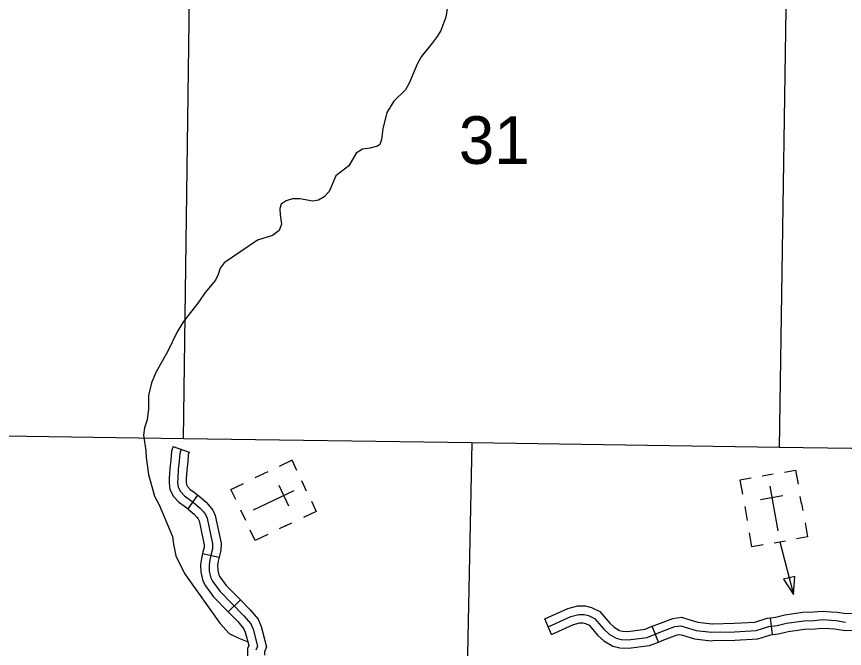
# Model space of a CAD drawing. Extents: x 0 to 3171, y 0 to 2059.
# Drawn here: x 1380.6 to 1502.8, y 562 to 655.3 of the extents above; entities that cross this region are included whole.
import ezdxf

# ---------------------------------------------------------------- set-up
doc = ezdxf.new("R2010")
doc.units = 0
for name, color, linetype in [('Level 32', 7, 'Continuous'), ('Level 35', 7, 'Continuous'), ('Level 4', 7, 'Continuous'), ('Level 45', 7, 'Continuous'), ('Level 5', 7, 'Continuous'), ('Level 57', 7, 'Continuous')]:
    doc.layers.add(name, color=color, linetype=linetype)

msp = doc.modelspace()

# ---------------------------------------------------------------- linework, layer by layer
at = {"layer": 'Level 32'}
for p, q in [((1403.73, 591.84), (1406.08, 591)), ((1405.9, 582.62), (1407.37, 584.64)), ((1408.03, 576.03), (1410.48, 575.52)), ((1411.84, 567.43), (1413.62, 569.18))]:
    msp.add_line(p, q, dxfattribs=at)
for points in [[(1403.73, 591.84), (1403.48, 591.13), (1403.36, 589.81), (1403.21, 588.55), (1403.14, 587.15), (1403.12, 586.49), (1403.21, 585.49), (1403.74, 584.47), (1404.53, 583.63), (1405.36, 583), (1405.9, 582.62)], [(1404.91, 591.42), (1404.71, 590.86), (1404.6, 589.68), (1404.45, 588.45), (1404.39, 587.1), (1404.37, 586.53), (1404.43, 585.85), (1404.77, 585.2), (1405.36, 584.56), (1406.1, 584.01), (1406.71, 583.57), (1407.69, 582.74), (1408.17, 582.17), (1408.47, 581.79), (1408.72, 581.24), (1409.53, 577.45), (1409.51, 576.72), (1409.3, 576), (1409.12, 575.11), (1409.02, 574.36), (1409.04, 573.42), (1409.27, 572.44), (1409.53, 571.94), (1410.58, 570.5), (1414.15, 566.86), (1415.17, 565.65), (1415.53, 564.87), (1416.16, 562.36), (1415.92, 561.76)], [(1406.08, 591), (1405.94, 590.59), (1405.85, 589.55), (1405.7, 588.35), (1405.64, 587.05), (1405.62, 586.56), (1405.66, 586.21), (1405.8, 585.92), (1406.2, 585.5), (1406.84, 585.02), (1407.37, 584.64)], [(1407.37, 584.64), (1407.49, 584.55), (1408.57, 583.63), (1409.14, 582.96), (1409.54, 582.45), (1409.91, 581.64), (1410.79, 577.56), (1410.75, 576.53), (1410.52, 575.7), (1410.48, 575.52)], [(1405.9, 582.62), (1405.94, 582.58), (1406.8, 581.86), (1407.2, 581.38), (1407.39, 581.14), (1407.53, 580.84), (1408.28, 577.34), (1408.26, 576.92), (1408.09, 576.29), (1408.03, 576.03)], [(1408.03, 576.03), (1407.89, 575.32), (1407.76, 574.43), (1407.8, 573.26), (1408.09, 571.99), (1408.47, 571.28), (1409.62, 569.69), (1411.84, 567.43)], [(1410.48, 575.52), (1410.35, 574.9), (1410.27, 574.29), (1410.29, 573.59), (1410.45, 572.88), (1410.6, 572.6), (1411.53, 571.31), (1413.62, 569.18)], [(1413.62, 569.18), (1415.08, 567.7), (1416.24, 566.32), (1416.71, 565.28), (1417.47, 562.27), (1417.17, 561.52), (1417.17, 561.01), (1417.17, 561.03)], [(1411.84, 567.43), (1413.23, 566.02), (1414.11, 564.98), (1414.34, 564.45), (1414.85, 562.44), (1414.67, 562), (1414.67, 560.64), (1414.77, 560.31)]]:
    msp.add_lwpolyline(points, dxfattribs=at)
at = {"layer": 'Level 35'}
for points in [[(1444.22, 657.05), (1443.95, 655.21), (1443.19, 653.22), (1442.68, 652.37), (1441.94, 651.36), (1440.32, 649.35), (1439.73, 648.25), (1438.59, 645.54), (1438.01, 644.45), (1436.25, 642.79), (1435.25, 641.13), (1434.65, 638.71), (1434.46, 637.12), (1434.2, 636.42), (1433.87, 636.14), (1432.74, 635.86), (1431.65, 635.74), (1430.7, 635.13), (1429.64, 633.25), (1427.71, 631.79), (1426.72, 629.45), (1426, 628.66), (1425.14, 628.21), (1424.33, 628.05), (1422.41, 628.4), (1421.3, 628.38), (1420.37, 628.07), (1419.66, 627.58), (1419.47, 626.95), (1419.49, 626), (1419.67, 624.65), (1419.36, 623.73), (1418.37, 622.96), (1416.15, 622.29), (1411.25, 618.92), (1410.63, 618.13), (1410.35, 617.21), (1409.93, 616.36), (1408.43, 614.57), (1407.47, 613.19), (1405.23, 610.28), (1404.28, 608.77), (1402.86, 605.79), (1401.22, 602.86), (1400.5, 601.24), (1400.08, 599.35), (1400.07, 597.39), (1399.85, 595.75), (1399.46, 594.6), (1399.32, 593.51), (1399.66, 591.26)], [(1399.66, 591.26), (1399.73, 590.2), (1400.06, 587.71), (1400.97, 584.51), (1401.62, 583.21), (1403.61, 578.57), (1403.75, 577.4), (1404.09, 575.7), (1405.37, 573.1), (1409.01, 567.98), (1410.59, 565.77), (1411.99, 564.25), (1413.4, 563.52), (1414.64, 563.07)]]:
    msp.add_lwpolyline(points, dxfattribs=at)
at = {"layer": 'Level 4'}
for points in [[(1405.23, 592.96), (1406.43, 680), (1406.44, 680.69), (1407.28, 729.83)], [(1405.23, 592.96), (1355.59, 593.71)], [(1514.5, 591.38), (1493.15, 591.69), (1447.76, 592.35), (1405.23, 592.96)]]:
    msp.add_lwpolyline(points, dxfattribs=at)
at = {"layer": 'Level 45'}
for p, q in [((1459.56, 564.09), (1458.53, 566.37)), ((1492.17, 564.06), (1491.83, 566.54)), ((1475.31, 562.97), (1474.37, 565.29))]:
    msp.add_line(p, q, dxfattribs=at)
for points in [[(1458.53, 566.37), (1461.95, 567.92), (1463.4, 568.3), (1464.51, 568.3), (1465.44, 568.05), (1466.66, 567.46), (1467.79, 566.14)], [(1459.04, 565.23), (1462.37, 566.74), (1463.56, 567.05), (1464.34, 567.05), (1465, 566.87), (1465.89, 566.45), (1467.24, 564.86), (1468.03, 564.15), (1469.07, 563.52), (1469.81, 563.33), (1470.83, 563.29), (1473.67, 563.65), (1475.68, 564.47), (1477.74, 565.24), (1478.61, 565.37), (1479.24, 565.15), (1480.87, 564.66), (1483.14, 564.43), (1486.54, 564.48), (1489.75, 564.67), (1491.61, 565.25), (1492.82, 565.42), (1494.21, 565.75), (1496.75, 566.11), (1498.29, 566.17), (1499.51, 566.29), (1501.52, 566.14), (1502.92, 565.91)], [(1491.83, 566.54), (1492.59, 566.65), (1493.97, 566.98), (1496.64, 567.36), (1498.21, 567.42), (1499.5, 567.54), (1500.81, 567.45)], [(1500.81, 567.45), (1501.67, 567.39), (1503, 567.17), (1504.62, 567.23), (1509.21, 568.02)], [(1459.56, 564.09), (1462.79, 565.56), (1463.73, 565.8), (1464.18, 565.8), (1464.56, 565.7), (1465.11, 565.44), (1465.89, 564.52)], [(1467.79, 566.14), (1468.14, 565.73), (1468.77, 565.16), (1469.56, 564.69), (1470, 564.58), (1470.78, 564.54), (1473.35, 564.87), (1474.37, 565.29)], [(1474.37, 565.29), (1475.22, 565.63), (1477.43, 566.46), (1478.73, 566.65), (1479.63, 566.34), (1481.12, 565.89), (1483.19, 565.68), (1483.28, 565.68)], [(1483.28, 565.68), (1486.5, 565.73), (1489.52, 565.91), (1491.34, 566.47), (1491.83, 566.54)], [(1465.89, 564.52), (1466.34, 563.99), (1467.28, 563.14), (1468.59, 562.36), (1469.63, 562.09), (1470.89, 562.04), (1473.99, 562.44), (1475.31, 562.97)], [(1492.17, 564.06), (1493.05, 564.19), (1494.44, 564.52), (1496.86, 564.87), (1498.37, 564.93), (1499.53, 565.04), (1500.63, 564.96)], [(1500.63, 564.96), (1501.37, 564.9), (1502.85, 564.66), (1504.89, 564.74), (1509.64, 565.56)], [(1475.31, 562.97), (1476.13, 563.3), (1478.06, 564.02), (1478.49, 564.09), (1478.85, 563.97), (1480.62, 563.43), (1483.09, 563.17), (1483.32, 563.18)], [(1483.32, 563.18), (1486.59, 563.23), (1489.97, 563.43), (1491.88, 564.02), (1492.17, 564.06)]]:
    msp.add_lwpolyline(points, dxfattribs=at)
at = {"layer": 'Level 5'}
for points in [[(1494.45, 679.13), (1493.15, 591.69)], [(1447.76, 592.35), (1446.73, 542)]]:
    msp.add_lwpolyline(points, dxfattribs=at)
at = {"layer": 'Level 57'}
for p, q in [((1417.66, 588.08), (1415.78, 587.19)), ((1492.27, 587.75), (1490.63, 587.45)), ((1423.4, 585.26), (1422.68, 586.77)), ((1421.53, 585.31), (1415.51, 582.45)), ((1419.31, 586.1), (1420.75, 583.07)), ((1491.74, 585.96), (1492.92, 579.4)), ((1490.4, 584.02), (1493.69, 584.62)), ((1496.43, 583.42), (1496.25, 584.43)), ((1418.52, 583.88), (1418.52, 583.88)), ((1418.52, 583.88), (1418.52, 583.88)), ((1488.05, 582.95), (1488.42, 580.9)), ((1496.43, 583.42), (1496.62, 582.38)), ((1413.65, 582.48), (1414.36, 580.97)), ((1492.33, 582.68), (1492.33, 582.68)), ((1492.33, 582.68), (1492.33, 582.68)), ((1420.3, 580.11), (1421.23, 580.55)), ((1420.3, 580.11), (1419.35, 579.66)), ((1492.41, 577.61), (1494.05, 577.91))]:
    msp.add_line(p, q, dxfattribs=at)
for points in [[(1421.96, 588.28), (1421.25, 589.79), (1419.37, 588.89)], [(1493.91, 588.04), (1495.55, 588.34), (1495.92, 586.29)], [(1488.98, 587.16), (1487.34, 586.86), (1487.71, 584.81)], [(1412.93, 583.99), (1412.22, 585.5), (1414.1, 586.39)], [(1424.11, 583.76), (1424.82, 582.26), (1422.94, 581.36)], [(1496.95, 580.55), (1497.32, 578.5), (1495.68, 578.2)], [(1417.67, 578.86), (1415.79, 577.97), (1415.07, 579.48)], [(1490.76, 577.31), (1489.12, 577.02), (1488.75, 579.07)], [(1493.23, 577.76), (1495.24, 569.97)]]:
    msp.add_lwpolyline(points, dxfattribs=at)
msp.add_lwpolyline([(1495.43, 572.65), (1493.78, 572.23), (1495.24, 569.97)], close=True, dxfattribs=at)

# ---------------------------------------------------------------- texts
at = {"layer": 'Level 5'}
msp.add_text('31', height=7.04, dxfattribs=at).set_placement((1445.86, 633.54))

doc.saveas('drawing.dxf')
